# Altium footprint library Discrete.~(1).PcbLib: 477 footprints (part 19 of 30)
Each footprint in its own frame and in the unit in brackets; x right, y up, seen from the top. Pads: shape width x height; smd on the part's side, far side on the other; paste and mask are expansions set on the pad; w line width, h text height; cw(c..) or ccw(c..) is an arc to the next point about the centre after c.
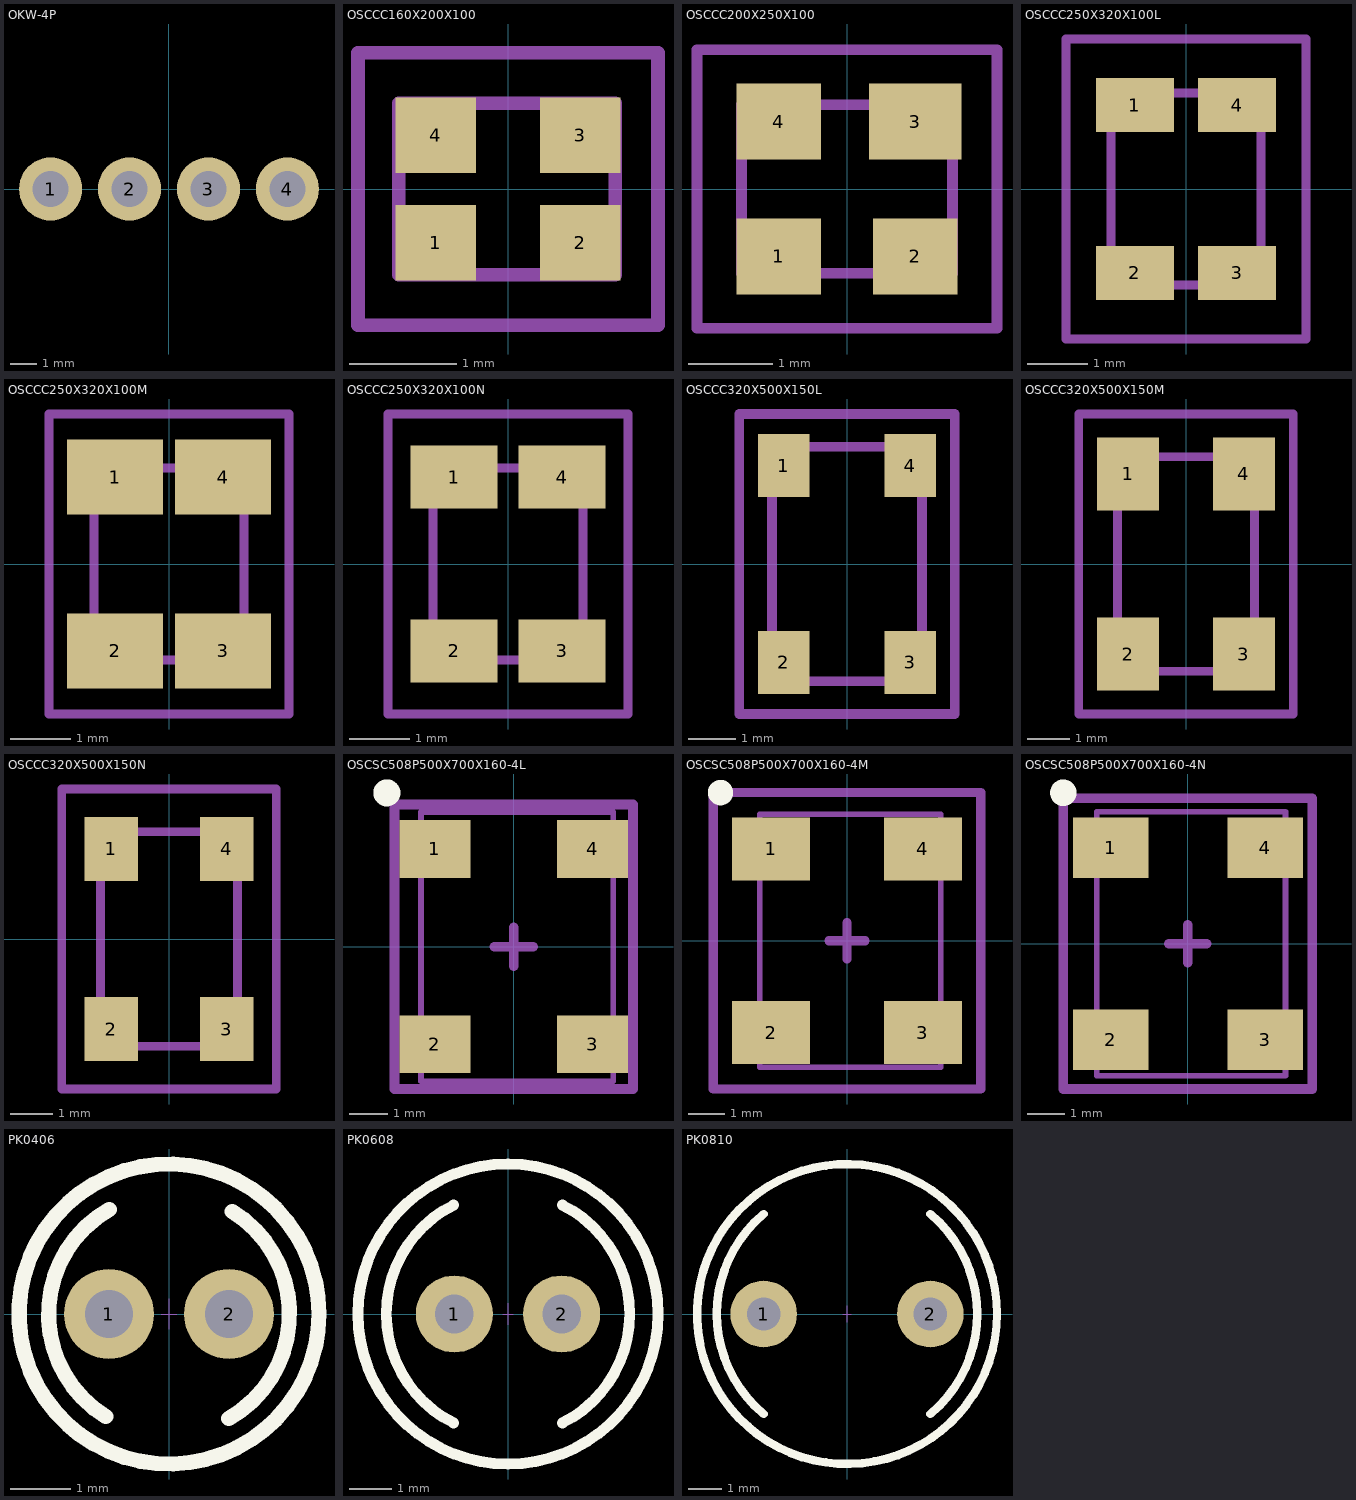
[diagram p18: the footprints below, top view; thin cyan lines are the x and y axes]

## OKW-4P [mm]
pads (4):
  round 2.4 hole 1.37: 1(-4.5,0) 2(-1.5,0) 3(1.5,0) 4(4.5,0)

## OSCCC160X200X100 [mm]
pads (4):
  rect 0.75x0.7 smd: 1(-0.675,-0.5) 2(0.675,-0.5) 3(0.675,0.5) 4(-0.675,0.5)
Mechanical 13:
  lines w0.127: -1.016,-0.8 1,-0.8 1,0.8 -1.016,0.8 -1.016,-0.8
Mechanical 15:
  lines w0.127: -1.397,-1.27 1.397,-1.27 1.397,1.27 -1.397,1.27 -1.397,0.381 -1.397,-1.27
3D body "User Library-NT2016SA-END4910A-48MHZ Crystal (NDK).STEP": height 0.7, standoff 0, extent -1,-0.8 1,0.8

## OSCCC200X250X100 [mm]
pads (4):
  rect 1x0.9 smd: 1(-0.81,-0.8) 2(0.81,-0.8) 4(-0.81,0.8)
  rect 1.1x0.9 smd: 3(0.81,0.8)
Mechanical 13:
  lines w0.127: -1.25,-1 1.25,-1 1.25,1 -1.25,1 -1.25,-1
Mechanical 15:
  lines w0.127: -1.778,-1.651 1.778,-1.651 1.778,1.651 -1.778,1.651 -1.778,0 -1.778,-1.524 -1.778,-1.651
3D body "User Library-SM2520-4.STEP": height 0.8, standoff -0.03, extent -1.25,-1 1.25,1

## OSCCC250X320X100L [mm]
pads (4):
  rect 1.3x0.9 smd: 1(-0.85,1.4) 2(-0.85,-1.4) 3(0.85,-1.4) 4(0.85,1.4)
Mechanical 13:
  lines w0.152: -1.25,-1.6 1.25,-1.6 1.25,1.6 -1.25,1.6 -1.25,-1.6
Mechanical 15:
  lines w0.152: -2,-2.5 2,-2.5 2,2.5 -2,2.5 -2,-2.5
3D body "User Library-User Library-Siward_SX3225.STEP": height 0.81, standoff 0, extent -1.25,-1.6 1.25,1.6

## OSCCC250X320X100M [mm]
pads (4):
  rect 1.6x1.25 smd: 1(-0.9,1.45) 2(-0.9,-1.45) 3(0.9,-1.45) 4(0.9,1.45)
Mechanical 13:
  lines w0.152: -1.25,-1.6 1.25,-1.6 1.25,1.6 -1.25,1.6 -1.25,-1.6
Mechanical 15:
  lines w0.152: -2,-2.5 2,-2.5 2,2.5 -2,2.5 -2,-2.5
3D body "User Library-User Library-Siward_SX3225.STEP": height 0.81, standoff 0, extent -1.25,-1.6 1.25,1.6

## OSCCC250X320X100N [mm]
pads (4):
  rect 1.45x1.05 smd: 1(-0.9,1.45) 2(-0.9,-1.45) 3(0.9,-1.45) 4(0.9,1.45)
Mechanical 13:
  lines w0.152: -1.25,-1.6 1.25,-1.6 1.25,1.6 -1.25,1.6 -1.25,-1.6
Mechanical 15:
  lines w0.152: -2,-2.5 2,-2.5 2,2.5 -2,2.5 -2,-2.5
3D body "User Library-User Library-Siward_SX3225.STEP": height 0.81, standoff 0, extent -1.25,-1.6 1.25,1.6

## OSCCC320X500X150L [mm]
pads (4):
  rect 1.1x1.35 smd: 1(-1.35,2.1) 2(-1.35,-2.1) 3(1.35,-2.1) 4(1.35,2.1)
Mechanical 13:
  lines w0.203: -1.6,-2.5 -1.6,2.5 1.6,2.5 1.6,-2.5 -1.6,-2.5
Mechanical 15:
  lines w0.203: -2.3,-3.2 -2.3,3.2 2.3,3.2 2.3,-3.2 -2.3,-3.2
3D body "User Library-CRYSTALSMD5X32.STEP": height 1, standoff 0, extent -1.6,-2.5 1.6,2.5

## OSCCC320X500X150M [mm]
pads (4):
  rect 1.45x1.7 smd: 1(-1.35,2.1) 2(-1.35,-2.1) 3(1.35,-2.1) 4(1.35,2.1)
Mechanical 13:
  lines w0.203: -1.6,-2.5 1.6,-2.5 1.6,2.5 -1.6,2.5 -1.6,-2.5
Mechanical 15:
  lines w0.203: -2.5,-3.5 2.5,-3.5 2.5,3.5 -2.5,3.5 -2.5,-3.5
3D body "User Library-CRYSTALSMD5X32.STEP": height 1, standoff 0, extent -1.6,-2.5 1.6,2.5

## OSCCC320X500X150N [mm]
pads (4):
  rect 1.25x1.5 smd: 1(-1.35,2.1) 2(-1.35,-2.1) 3(1.35,-2.1) 4(1.35,2.1)
Mechanical 13:
  lines w0.203: -1.6,-2.5 1.6,-2.5 1.6,2.5 -1.6,2.5 -1.6,-2.5
Mechanical 15:
  lines w0.203: -2.5,-3.5 2.5,-3.5 2.5,3.5 -2.5,3.5 -2.5,-3.5
3D body "User Library-CRYSTALSMD5X32.STEP": height 1, standoff 0, extent -1.6,-2.5 1.6,2.5

## OSCSC508P500X700X160-4L [mm]
pads (4):
  rect 1.85x1.5 smd: 1(-2.05,2.54) 2(-2.05,-2.54) 3(2.05,-2.54) 4(2.05,2.54)
Top Overlay:
  circle w0.5: c-3.3,4 r0.1
Mechanical 13:
  lines w0.152: -2.413,-3.5 2.587,-3.5 2.587,3.5 -2.413,3.5 -2.413,-3.5 ; -2.413,-3.5 -2.413,-3.5
Mechanical 15:
  lines w0.254: -0.5,0 0.5,0 ; 0,-0.5 0,0.5 ; -3.1,-3.7 3.1,-3.7 3.1,3.7 -3.1,3.7 -3.1,-3.7
3D body "User Library-CFPS72-73.STEP": height 1.51, standoff -0.01, extent -2.413,-3.5 2.587,3.5

## OSCSC508P500X700X160-4M [mm]
pads (4):
  rect 2.15x1.75 smd: 1(-2.1,2.54) 2(-2.1,-2.54) 3(2.1,-2.54) 4(2.1,2.54)
Top Overlay:
  circle w0.5: c-3.5,4.1 r0.1
Mechanical 13:
  lines w0.152: 2.587,-3.5 2.587,3.5 -2.413,3.5 -2.413,-3.5 2.587,-3.5 ; 2.587,-3.5 2.587,-3.5
Mechanical 15:
  lines w0.254: -0.5,0 0.5,0 ; 0,-0.5 0,0.5 ; -3.7,-4.1 -3.7,4.1 3.7,4.1 3.7,-4.1 -3.7,-4.1
3D body "User Library-CFPS72-73.STEP": height 1.51, standoff -0.01, extent -2.413,-3.5 2.587,3.5

## OSCSC508P500X700X160-4N [mm]
pads (4):
  rect 2x1.6 smd: 1(-2.05,2.54) 2(-2.05,-2.54) 3(2.05,-2.54) 4(2.05,2.54)
Top Overlay:
  circle w0.5: c-3.3,4 r0.1
Mechanical 13:
  lines w0.152: -2.413,-3.5 2.587,-3.5 2.587,3.5 -2.413,3.5 -2.413,-3.5
Mechanical 15:
  lines w0.254: -0.5,0 0.5,0 ; 0,-0.5 0,0.5 ; -3.3,-3.85 -3.3,3.85 3.3,3.85 3.3,-3.85 -3.3,-3.85
3D body "User Library-CFPS72-73.STEP": height 1.51, standoff -0.01, extent -2.413,-3.5 2.587,3.5

## PCBComponent_1 - duplicate [mm]

## PK0406 [mm] "2*5*8mm(脚距，直径，高）"
pads (2):
  round 1.5 hole 0.8: 1(-1,0) 2(1,0)
Top Overlay:
  circle w0.254: c0,0 r2.5
  lines w0.254: -1.052,-1.71 cw(c0,0) -0.996,1.743 ; 0.996,-1.743 ccw(c0,0) 1.052,1.71
Mechanical 15:
  lines w0.01: -0.127,0 0.127,0 ; 0,-0.254 0,0.254
3D body "PK0406.STEP": height 8.02, standoff -2.78, extent -2.5,-2.5 2.5,2.5

## PK0608 [mm] "2.5*7*10mm(脚距，直径，高）"
pads (2):
  round 1.8 hole 0.9: 1(-1.25,0) 2(1.25,0)
Top Overlay:
  circle w0.254: c0,0 r3.5
  lines w0.254: -1.27,-2.54 cw(c0,0) -1.27,2.54 ; 1.27,-2.54 ccw(c0,0) 1.27,2.54
Mechanical 15:
  lines w0.01: -0.127,0 0.127,0 ; 0,-0.254 0,0.254
3D body "PK0608.STEP": height 10.02, standoff -2.78, extent -3.5,-3.5 3.5,3.5

## PK0810 [mm] "5*9*12mm(脚距，直径，高）"
pads (2):
  round 2 hole 1: 1(-2.5,0) 2(2.5,0)
Top Overlay:
  circle w0.254: c0,0 r4.5
  lines w0.254: -2.5,-3 cw(c0,0) -2.5,3 ; 2.5,-3 ccw(c0,0) 2.5,3
Mechanical 15:
  lines w0.01: -0.127,0 0.127,0 ; 0,-0.254 0,0.254
3D body "PK0810.STEP": height 12.02, standoff -2.78, extent -4.5,-4.5 4.5,4.5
